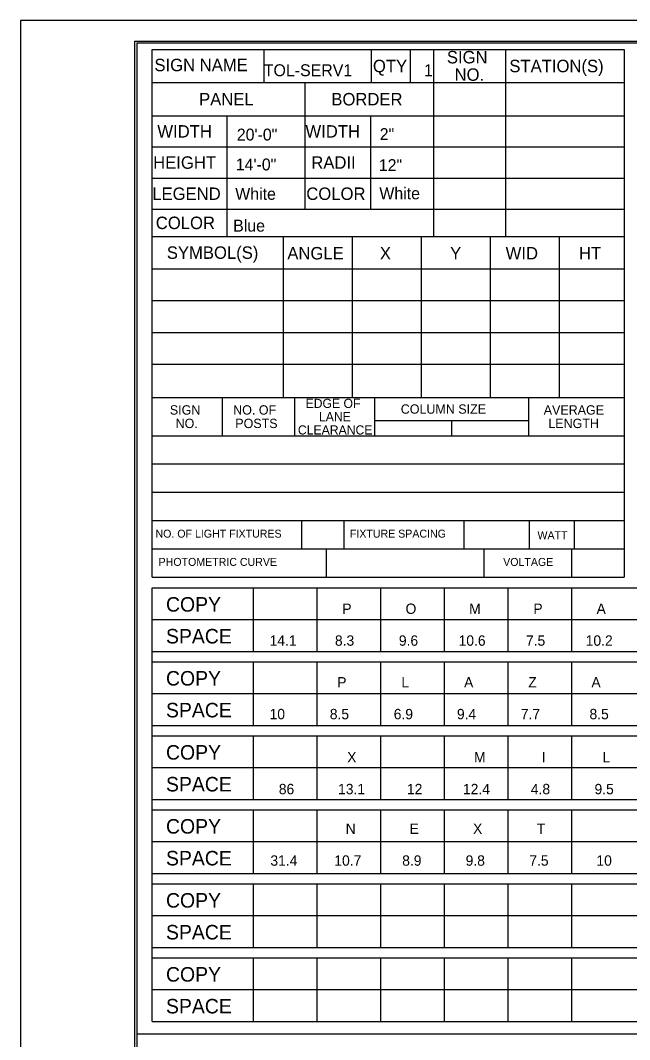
# Model space of a CAD drawing. Extents: x 17890628 to 17890817, y 17897493 to 17897992.
# Drawn here: x 17890655.57 to 17890684.37, y 17897548.59 to 17897596.75 of the extents above; entities that cross this region are included whole.
import ezdxf

# ---------------------------------------------------------------- set-up
doc = ezdxf.new("R2010")
doc.units = 0
for name, color, linetype in [('GSSign', 7, 'Continuous'), ('PlotBorder_dp', 7, 'Continuous'), ('SheetBorder_dp', 7, 'Continuous'), ('SheetLinesMisc1_dp', 7, 'Continuous'), ('SheetLinesMisc2_dp', 7, 'Continuous'), ('TextMinor', 7, 'Continuous')]:
    doc.layers.add(name, color=color, linetype=linetype)

msp = doc.modelspace()

# ---------------------------------------------------------------- linework, layer by layer
at = {"layer": 'PlotBorder_dp'}
msp.add_lwpolyline([(17890655.57, 17897492.839), (17890817.319, 17897492.839), (17890817.319, 17897596.75), (17890655.57, 17897596.75)], close=True, dxfattribs=at)
at = {"layer": 'SheetBorder_dp'}
for q in [(17890660.962, 17897493.819), (17890811.928, 17897595.77)]:
    msp.add_line((17890660.962, 17897595.77), q, dxfattribs=at)
at = {"layer": 'SheetLinesMisc1_dp'}
for p, q in [((17890667.098, 17897593.81), (17890667.098, 17897595.379)), ((17890672.146, 17897595.379), (17890672.146, 17897593.81)), ((17890673.998, 17897595.379), (17890673.998, 17897593.81)), ((17890675.102, 17897595.379), (17890675.102, 17897586.544)), ((17890678.497, 17897595.379), (17890678.497, 17897586.544)), ((17890661.804, 17897593.81), (17890684.115, 17897593.81)), ((17890669.015, 17897593.81), (17890669.015, 17897587.809)), ((17890661.804, 17897592.242), (17890684.115, 17897592.242)), ((17890665.33, 17897592.242), (17890665.33, 17897586.544)), ((17890672.126, 17897592.226), (17890672.126, 17897587.809)), ((17890661.804, 17897590.77), (17890684.115, 17897590.77)), ((17890661.804, 17897589.297), (17890684.115, 17897589.297)), ((17890661.804, 17897587.825), (17890684.115, 17897587.825)), ((17890661.804, 17897586.544), (17890684.115, 17897586.544)), ((17890668, 17897586.544), (17890668, 17897578.926)), ((17890671.26, 17897586.544), (17890671.26, 17897578.926)), ((17890674.52, 17897586.544), (17890674.52, 17897578.926)), ((17890677.78, 17897586.515), (17890677.78, 17897578.926)), ((17890681.04, 17897586.515), (17890681.04, 17897578.926)), ((17890661.809, 17897585.012), (17890684.115, 17897585.012)), ((17890661.809, 17897583.508), (17890684.115, 17897583.508)), ((17890661.809, 17897582.005), (17890684.115, 17897582.005)), ((17890661.809, 17897580.501), (17890684.115, 17897580.501)), ((17890661.804, 17897578.926), (17890684.115, 17897578.926)), ((17890665.115, 17897578.926), (17890665.115, 17897577.129)), ((17890668.537, 17897578.926), (17890668.537, 17897577.129)), ((17890672.315, 17897578.926), (17890672.315, 17897577.129)), ((17890679.591, 17897578.926), (17890679.591, 17897577.129)), ((17890672.315, 17897577.848), (17890679.586, 17897577.848)), ((17890675.951, 17897577.848), (17890675.951, 17897577.129)), ((17890661.804, 17897577.129), (17890684.115, 17897577.129)), ((17890661.804, 17897575.794), (17890684.115, 17897575.794)), ((17890661.804, 17897574.458), (17890684.115, 17897574.458)), ((17890661.804, 17897573.122), (17890684.115, 17897573.122)), ((17890661.804, 17897571.787), (17890684.115, 17897571.787))]:
    msp.add_line(p, q, dxfattribs=at)
at = {"layer": 'SheetLinesMisc2_dp'}
for p, q in [((17890661.083, 17897595.691), (17890811.539, 17897595.691)), ((17890661.083, 17897595.691), (17890661.083, 17897502.033)), ((17890661.804, 17897570.451), (17890661.804, 17897595.379)), ((17890661.804, 17897595.379), (17890684.115, 17897595.379)), ((17890684.115, 17897595.379), (17890684.115, 17897570.451)), ((17890661.804, 17897573.122), (17890684.11, 17897573.122)), ((17890668.863, 17897573.122), (17890668.863, 17897571.786)), ((17890670.855, 17897573.122), (17890670.855, 17897571.786)), ((17890676.53, 17897573.122), (17890676.53, 17897571.786)), ((17890679.617, 17897573.122), (17890679.617, 17897571.786)), ((17890681.746, 17897573.122), (17890681.746, 17897571.786)), ((17890661.804, 17897571.786), (17890684.11, 17897571.786)), ((17890670.032, 17897571.786), (17890670.032, 17897570.451)), ((17890677.475, 17897571.786), (17890677.475, 17897570.451)), ((17890681.617, 17897571.786), (17890681.617, 17897570.451)), ((17890661.804, 17897570.451), (17890684.11, 17897570.451)), ((17890661.804, 17897570.451), (17890684.115, 17897570.451)), ((17890661.804, 17897569.94), (17890735.8, 17897569.94)), ((17890661.804, 17897549.452), (17890661.804, 17897569.94)), ((17890666.568, 17897569.94), (17890666.568, 17897566.933)), ((17890669.578, 17897569.94), (17890669.578, 17897566.933)), ((17890672.588, 17897569.94), (17890672.588, 17897566.933)), ((17890675.598, 17897569.94), (17890675.598, 17897566.933)), ((17890678.608, 17897569.94), (17890678.608, 17897566.933)), ((17890681.618, 17897569.94), (17890681.618, 17897566.933)), ((17890661.804, 17897568.437), (17890735.8, 17897568.437)), ((17890661.804, 17897566.933), (17890735.8, 17897566.933)), ((17890661.804, 17897566.443), (17890735.8, 17897566.443)), ((17890666.568, 17897566.443), (17890666.568, 17897563.437)), ((17890669.578, 17897566.443), (17890669.578, 17897563.437)), ((17890672.588, 17897566.443), (17890672.588, 17897563.437)), ((17890675.598, 17897566.443), (17890675.598, 17897563.437)), ((17890678.608, 17897566.443), (17890678.608, 17897563.437)), ((17890681.618, 17897566.443), (17890681.618, 17897563.437)), ((17890661.804, 17897564.94), (17890735.8, 17897564.94)), ((17890661.804, 17897563.437), (17890735.8, 17897563.437)), ((17890661.804, 17897562.947), (17890735.8, 17897562.947)), ((17890666.568, 17897562.947), (17890666.568, 17897559.941)), ((17890669.578, 17897562.947), (17890669.578, 17897559.941)), ((17890672.588, 17897562.947), (17890672.588, 17897559.941)), ((17890675.598, 17897562.947), (17890675.598, 17897559.941)), ((17890678.608, 17897562.947), (17890678.608, 17897559.941)), ((17890681.618, 17897562.947), (17890681.618, 17897559.941)), ((17890661.804, 17897561.444), (17890735.8, 17897561.444)), ((17890661.804, 17897559.941), (17890735.8, 17897559.941)), ((17890661.804, 17897559.451), (17890735.8, 17897559.451)), ((17890666.568, 17897559.451), (17890666.568, 17897556.444)), ((17890669.578, 17897559.451), (17890669.578, 17897556.444)), ((17890672.588, 17897559.451), (17890672.588, 17897556.444)), ((17890675.598, 17897559.451), (17890675.598, 17897556.444)), ((17890678.608, 17897559.451), (17890678.608, 17897556.444)), ((17890681.618, 17897559.451), (17890681.618, 17897556.444)), ((17890661.804, 17897557.947), (17890735.8, 17897557.947)), ((17890661.804, 17897556.444), (17890735.8, 17897556.444)), ((17890661.804, 17897555.954), (17890735.8, 17897555.954)), ((17890666.568, 17897555.954), (17890666.568, 17897552.948)), ((17890669.578, 17897555.954), (17890669.578, 17897552.948)), ((17890672.588, 17897555.954), (17890672.588, 17897552.948)), ((17890675.598, 17897555.954), (17890675.598, 17897552.948)), ((17890678.608, 17897555.954), (17890678.608, 17897552.948)), ((17890681.618, 17897555.954), (17890681.618, 17897552.948)), ((17890661.804, 17897554.451), (17890735.8, 17897554.451)), ((17890661.804, 17897552.948), (17890735.8, 17897552.948)), ((17890661.804, 17897552.458), (17890735.8, 17897552.458)), ((17890666.568, 17897552.458), (17890666.568, 17897549.452)), ((17890669.578, 17897552.458), (17890669.578, 17897549.452)), ((17890672.588, 17897552.458), (17890672.588, 17897549.452)), ((17890675.598, 17897552.458), (17890675.598, 17897549.452)), ((17890678.608, 17897552.458), (17890678.608, 17897549.452)), ((17890681.618, 17897552.458), (17890681.618, 17897549.452)), ((17890661.804, 17897550.955), (17890735.8, 17897550.955)), ((17890661.804, 17897549.452), (17890735.8, 17897549.452)), ((17890661.083, 17897548.861), (17890736.311, 17897548.861))]:
    msp.add_line(p, q, dxfattribs=at)

# ---------------------------------------------------------------- texts
at = {"layer": 'GSSign'}
for s, height, p in [('TOL-SERV1', 0.5624, (17890667.078, 17897594.114)), ('1', 0.562, (17890674.65, 17897594.113)), ('20\'-0"', 0.5624, (17890665.801, 17897591.074)), ('2"', 0.5624, (17890672.558, 17897591.095)), ('14\'-0"', 0.5624, (17890665.753, 17897589.661)), ('12"', 0.5624, (17890672.515, 17897589.63)), ('White', 0.5624, (17890665.728, 17897588.274)), ('White', 0.5624, (17890672.54, 17897588.296)), ('Blue', 0.5624, (17890665.629, 17897586.77)), ('P', 0.49, (17890670.791, 17897568.706)), ('O', 0.49, (17890673.778, 17897568.706)), ('M', 0.49, (17890676.788, 17897568.706)), ('P', 0.49, (17890679.822, 17897568.706)), ('A', 0.49, (17890682.809, 17897568.706)), ('14.1', 0.4902, (17890667.349, 17897567.203)), ('8.3', 0.4902, (17890670.441, 17897567.203)), ('9.6', 0.4902, (17890673.463, 17897567.203)), ('10.6', 0.4902, (17890676.287, 17897567.203)), ('7.5', 0.4902, (17890679.472, 17897567.203)), ('10.2', 0.4902, (17890682.296, 17897567.203)), ('P', 0.49, (17890670.548, 17897565.233)), ('L', 0.49, (17890673.582, 17897565.233)), ('A', 0.49, (17890676.546, 17897565.233)), ('Z', 0.49, (17890679.579, 17897565.233)), ('A', 0.49, (17890682.566, 17897565.233)), ('10', 0.4902, (17890667.351, 17897563.73)), ('8.5', 0.4902, (17890670.198, 17897563.73)), ('6.9', 0.4902, (17890673.22, 17897563.73)), ('9.4', 0.4902, (17890676.207, 17897563.73)), ('7.7', 0.4902, (17890679.229, 17897563.73)), ('8.5', 0.4902, (17890682.475, 17897563.73)), ('X', 0.49, (17890671.021, 17897561.69)), ('M', 0.49, (17890677.018, 17897561.69)), ('I', 0.49, (17890680.215, 17897561.69)), ('L', 0.49, (17890683.085, 17897561.69)), ('86', 0.4902, (17890667.788, 17897560.187)), ('13.1', 0.4902, (17890670.589, 17897560.187)), ('12', 0.4902, (17890673.844, 17897560.187)), ('12.4', 0.4902, (17890676.493, 17897560.187)), ('4.8', 0.4902, (17890679.702, 17897560.187)), ('9.5', 0.4902, (17890682.712, 17897560.187)), ('N', 0.49, (17890670.949, 17897558.313)), ('E', 0.49, (17890673.971, 17897558.313)), ('X', 0.49, (17890676.969, 17897558.313)), ('T', 0.49, (17890679.98, 17897558.313)), ('31.4', 0.4902, (17890667.39, 17897556.81)), ('10.7', 0.4902, (17890670.412, 17897556.81)), ('8.9', 0.4902, (17890673.621, 17897556.81)), ('9.8', 0.4902, (17890676.619, 17897556.81)), ('7.5', 0.4902, (17890679.63, 17897556.81)), ('10', 0.4902, (17890682.803, 17897556.81))]:
    msp.add_text(s, height=height, dxfattribs=at).set_placement(p)
at = {"layer": 'TextMinor'}
for s, height, p in [('SIGN NAME', 0.5882, (17890661.908, 17897594.349)), ('SIGN', 0.5882, (17890675.733, 17897594.718)), ('STATION(S)', 0.5882, (17890678.686, 17897594.3)), ('QTY', 0.5882, (17890672.237, 17897594.3)), ('NO.', 0.5882, (17890676.096, 17897593.895)), ('PANEL', 0.5882, (17890664.018, 17897592.732)), ('BORDER', 0.5882, (17890670.271, 17897592.732)), ('WIDTH', 0.5882, (17890662.045, 17897591.212)), ('WIDTH', 0.5882, (17890669.048, 17897591.212)), ('HEIGHT', 0.5882, (17890661.848, 17897589.739)), ('RADII', 0.5882, (17890669.324, 17897589.739)), ('LEGEND', 0.5882, (17890661.806, 17897588.267)), ('COLOR', 0.5882, (17890669.088, 17897588.267)), ('COLOR', 0.5882, (17890661.973, 17897586.89)), ('SYMBOL(S)', 0.5882, (17890662.494, 17897585.484)), ('ANGLE', 0.5882, (17890668.19, 17897585.455)), ('X', 0.588, (17890672.565, 17897585.455)), ('Y', 0.588, (17890675.885, 17897585.455)), ('WID', 0.5882, (17890678.512, 17897585.455)), ('HT', 0.5882, (17890681.978, 17897585.455)), ('SIGN', 0.4411, (17890662.637, 17897578.125)), ('NO. OF', 0.4411, (17890665.63, 17897578.125)), ('EDGE OF', 0.4313, (17890669.052, 17897578.439)), ('COLUMN SIZE', 0.44113, (17890673.553, 17897578.166)), ('AVERAGE', 0.4411, (17890680.311, 17897578.125)), ('LANE', 0.4313, (17890669.685, 17897577.812)), ('NO.', 0.4411, (17890662.91, 17897577.488)), ('POSTS', 0.4411, (17890665.73, 17897577.488)), ('CLEARANCE', 0.4313, (17890668.69, 17897577.184)), ('LENGTH', 0.4411, (17890680.529, 17897577.488)), ('NO. OF LIGHT FIXTURES', 0.37485, (17890661.958, 17897572.312)), ('FIXTURE SPACING', 0.37485, (17890671.149, 17897572.312)), ('WATT', 0.3749, (17890680.015, 17897572.237)), ('PHOTOMETRIC CURVE', 0.37485, (17890662.105, 17897570.977)), ('VOLTAGE', 0.3749, (17890678.394, 17897570.976)), ('COPY', 0.6862, (17890662.454, 17897568.815)), ('SPACE', 0.6862, (17890662.454, 17897567.311)), ('COPY', 0.6862, (17890662.454, 17897565.322)), ('SPACE', 0.6862, (17890662.454, 17897563.819)), ('COPY', 0.6862, (17890662.454, 17897561.823)), ('SPACE', 0.6862, (17890662.454, 17897560.319)), ('COPY', 0.6862, (17890662.454, 17897558.327)), ('SPACE', 0.6862, (17890662.454, 17897556.823)), ('COPY', 0.6862, (17890662.454, 17897554.83)), ('SPACE', 0.6862, (17890662.454, 17897553.326)), ('COPY', 0.6862, (17890662.454, 17897551.334)), ('SPACE', 0.6862, (17890662.454, 17897549.831))]:
    msp.add_text(s, height=height, dxfattribs=at).set_placement(p)

doc.saveas('drawing.dxf')
